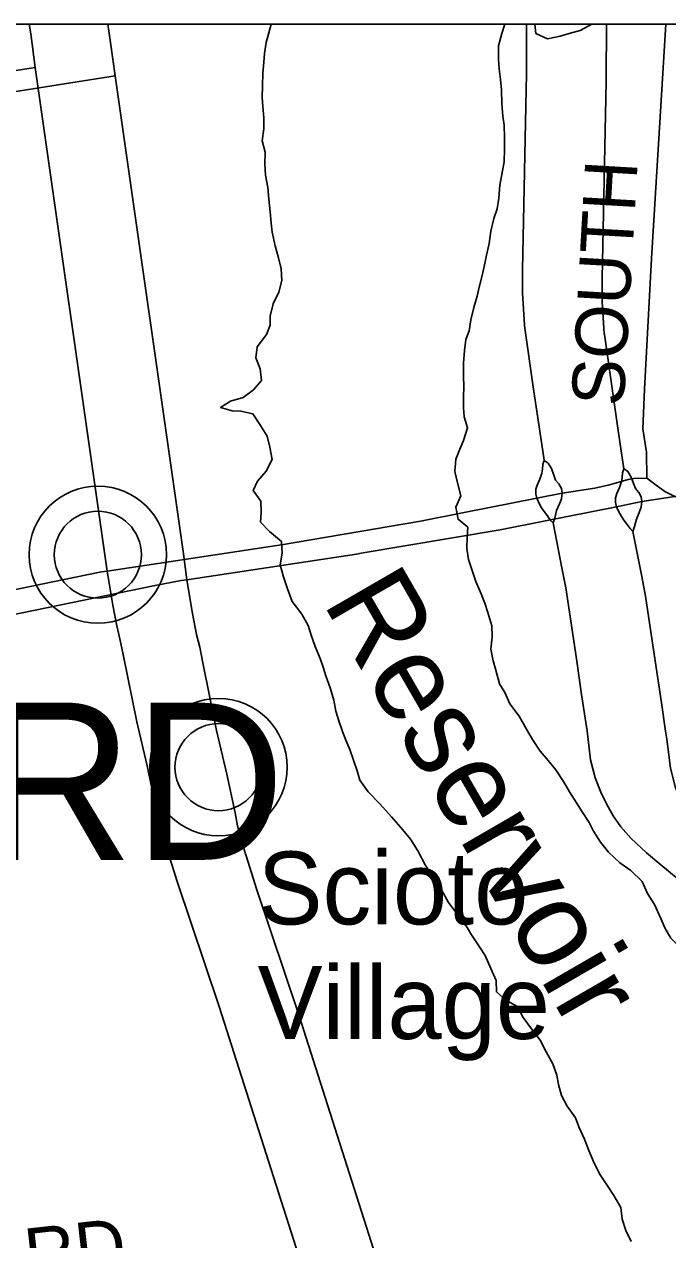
# Model space of a CAD drawing. Extents: x -38.2 to 41.9, y -4 to 24.9.
# Drawn here: x 3.416 to 4.114, y 19.582 to 20.9 of the extents above; entities that cross this region are included whole.
import ezdxf

# ---------------------------------------------------------------- set-up
doc = ezdxf.new("R2010")
doc.units = 0
for name, color, linetype in [('GM_X_County_Road', 7, 'Continuous'), ('GM_X_County_Road_Text', 7, 'Continuous'), ('GM_X_Interchange_Ramps', 7, 'Continuous'), ('GM_X_Major_Lake', 7, 'Continuous'), ('GM_X_Major_Lake_Text', 7, 'Continuous'), ('GM_X_Major_River', 7, 'Continuous'), ('GM_X_Minor_Lake', 7, 'Continuous'), ('GM_X_State_Location', 7, 'Continuous'), ('GM_X_State_Route', 7, 'Continuous'), ('GM_X_Township_Road', 7, 'Continuous'), ('GM_X_Township_Road_Text', 7, 'Continuous'), ('GM_X_Township_Text', 7, 'Continuous'), ('GM_X_Unincorporated', 7, 'Continuous'), ('GM_X_Unincorporated_Location', 7, 'Continuous'), ('GM_X_Unincorporated_Text', 7, 'Continuous'), ('SH_Cut_Line', 7, 'Continuous'), ('SH_Data', 7, 'Continuous')]:
    doc.layers.add(name, color=color, linetype=linetype)

msp = doc.modelspace()

# ---------------------------------------------------------------- linework, layer by layer
at = {"layer": 'GM_X_County_Road'}
for points in [[(4.0912, 20.4078), (4.091, 20.4359), (4.0868, 20.4612), (4.0885, 20.5043), (4.0927, 20.5786), (4.0963, 20.646), (4.1118, 20.9)], [(3.9993, 20.3916), (4.0349, 20.3972), (4.0506, 20.4007), (4.0709, 20.4065), (4.0772, 20.4075), (4.0912, 20.4078), (4.1, 20.4012), (4.1107, 20.3935), (4.1215, 20.388), (4.1348, 20.3832), (4.1455, 20.3808), (4.1717, 20.3782), (4.27, 20.374), (4.6996, 20.3515), (4.8642, 20.3433), (5.066, 20.3327)], [(3.893, 20.3705), (3.9719, 20.3861), (3.9993, 20.3916)], [(3.695, 20.3356), (3.8457, 20.3611), (3.893, 20.3705)], [(3.5061, 20.3069), (3.69, 20.3348), (3.695, 20.3356)], [(2.5521, 20.2867), (2.6398, 20.2826), (2.7282, 20.2767), (2.7828, 20.2748), (2.8413, 20.2694), (3.126, 20.2377), (3.1394, 20.236), (3.1753, 20.2401), (3.3558, 20.2767), (3.47, 20.3002), (3.5, 20.3062), (3.5061, 20.3069)]]:
    msp.add_lwpolyline(points, dxfattribs=at)
at = {"layer": 'GM_X_Interchange_Ramps'}
for p, q in [((4.0471, 20.8404), (4.0475, 20.9)), ((4.0857, 20.3013), (4.076, 20.3502))]:
    msp.add_line(p, q, dxfattribs=at)
for points in [[(5.0183, 19.2401), (5.0869, 20.3321), (5.1243, 20.9), (2.1103, 20.9), (2.1124, 20.4526), (2.1223, 20.2725), (2.1339, 19.396)], [(5.1048, 19.2309), (5.1734, 20.3229), (5.2114, 20.9), (2.1968, 20.9), (2.1989, 20.4434), (2.2088, 20.2633), (2.2204, 19.3868)], [(3.5926, 20.2977), (3.5887, 20.3257), (3.5146, 20.8441), (3.5096, 20.8803), (3.5068, 20.9)], [(4.0451, 20.5648), (4.0429, 20.5991), (4.0429, 20.6247), (4.0471, 20.8375), (4.0471, 20.8404)], [(4.0605, 20.457), (4.0549, 20.495), (4.0452, 20.5638), (4.0451, 20.5648)], [(4.0665, 20.418), (4.0664, 20.4181), (4.0605, 20.457)], [(4.076, 20.3502), (4.073, 20.3532), (4.0699, 20.3577), (4.0662, 20.3624), (4.0636, 20.3664), (4.0609, 20.3712), (4.0583, 20.3769), (4.0573, 20.3814), (4.0572, 20.3867), (4.0587, 20.3911), (4.0616, 20.3976), (4.0637, 20.4041), (4.0646, 20.4084), (4.0648, 20.4137), (4.0664, 20.4181)], [(4.0858, 20.3824), (4.0852, 20.3875), (4.0824, 20.3924), (4.0788, 20.3966), (4.0767, 20.4019), (4.0742, 20.4091), (4.0707, 20.415), (4.0665, 20.418)], [(4.076, 20.3502), (4.078, 20.3554), (4.0799, 20.3635), (4.0828, 20.3708), (4.0852, 20.3764), (4.0858, 20.3824)], [(3.9757, 18.9381), (3.9569, 19.007), (3.9527, 19.026), (3.8955, 19.2331), (3.8592, 19.3597), (3.8326, 19.4508), (3.8055, 19.539), (3.714, 19.8259), (3.6685, 19.9614), (3.651, 20.0166), (3.6474, 20.0308), (3.6447, 20.045), (3.636, 20.0869), (3.6248, 20.1343), (3.61, 20.2076), (3.6064, 20.2246), (3.6031, 20.2385), (3.5987, 20.261), (3.5926, 20.2977)], [(4.1013, 20.2027), (4.0899, 20.2798), (4.0857, 20.3013)], [(4.1116, 20.1336), (4.107, 20.1641), (4.1013, 20.2027)], [(4.3154, 19.8785), (4.3094, 19.8837), (4.247, 19.9344), (4.1928, 19.9793), (4.1772, 19.9923), (4.1603, 20.0082), (4.1494, 20.0207), (4.1411, 20.0325), (4.1341, 20.0455), (4.1278, 20.0582), (4.1218, 20.0737), (4.1167, 20.0933), (4.113, 20.1247), (4.1116, 20.1336)]]:
    msp.add_lwpolyline(points, dxfattribs=at)
at = {"layer": 'GM_X_Major_Lake'}
for points in [[(3.9573, 19.823), (3.9509, 19.8351), (3.9384, 19.842), (3.9282, 19.8508), (3.9279, 19.8633), (3.9219, 19.8762), (3.9159, 19.8902), (3.9098, 19.8997), (3.9012, 19.9127), (3.8955, 19.9225), (3.8861, 19.9347), (3.8763, 19.9476), (3.8687, 19.9613), (3.86, 19.9742), (3.851, 19.9887), (3.8431, 20.0039), (3.8348, 20.0164), (3.8246, 20.029), (3.8144, 20.0408), (3.8019, 20.0549), (3.7891, 20.0678), (3.78, 20.0804), (3.777, 20.0906), (3.7733, 20.102), (3.7691, 20.1138), (3.765, 20.1236), (3.7613, 20.1331), (3.7568, 20.1457), (3.7541, 20.1552), (3.7519, 20.1673), (3.7478, 20.1806), (3.7433, 20.1935), (3.7403, 20.203), (3.7369, 20.2125), (3.7317, 20.2254), (3.7272, 20.2376), (3.7242, 20.2482), (3.717, 20.2604), (3.7068, 20.274), (3.7016, 20.2877), (3.6974, 20.301), (3.6937, 20.3139), (3.696, 20.3264), (3.695, 20.3393), (3.6821, 20.35), (3.6723, 20.3603), (3.6731, 20.3709), (3.6727, 20.383), (3.6644, 20.3944), (3.669, 20.4047), (3.6786, 20.4156), (3.6851, 20.4281), (3.6825, 20.4414), (3.6795, 20.4535), (3.6723, 20.4649), (3.6641, 20.4775), (3.6512, 20.4806), (3.6417, 20.481), (3.6291, 20.4845), (3.6398, 20.4913), (3.6535, 20.4954), (3.6649, 20.5037), (3.6733, 20.5139), (3.6719, 20.5264), (3.6674, 20.5382), (3.6689, 20.5503), (3.6789, 20.5635), (3.6827, 20.5737), (3.6828, 20.5836), (3.6862, 20.5969), (3.6924, 20.6094), (3.6955, 20.6222), (3.6948, 20.6348), (3.6918, 20.6469), (3.6884, 20.6598), (3.6851, 20.6746), (3.684, 20.6845), (3.6829, 20.6966), (3.6814, 20.7103), (3.6803, 20.7232), (3.6777, 20.7365), (3.677, 20.7483), (3.6775, 20.7612), (3.6741, 20.7737), (3.676, 20.7866), (3.6761, 20.7987), (3.675, 20.8109), (3.6743, 20.8207), (3.6744, 20.8333), (3.6748, 20.8469), (3.676, 20.8591), (3.6768, 20.8685), (3.6784, 20.8803), (3.6814, 20.8909), (3.684, 20.9)], [(3.9373, 20.9), (3.934, 20.8901), (3.9305, 20.8765), (3.9305, 20.8617), (3.9312, 20.8518), (3.9326, 20.84), (3.9337, 20.829), (3.9341, 20.8142), (3.9351, 20.8005), (3.9366, 20.7907), (3.9369, 20.777), (3.9369, 20.7645), (3.9364, 20.7508), (3.9337, 20.7353), (3.9318, 20.7254), (3.9306, 20.7114), (3.929, 20.7), (3.9255, 20.6894), (3.9221, 20.6758), (3.9201, 20.6625), (3.9174, 20.6496), (3.915, 20.6375), (3.9127, 20.6277), (3.9096, 20.6148), (3.9073, 20.6053), (3.9038, 20.5928), (3.9004, 20.5795), (3.8984, 20.5678), (3.8949, 20.5583), (3.8934, 20.5462), (3.8926, 20.5326), (3.8925, 20.5193), (3.8928, 20.5064), (3.8924, 20.4969), (3.8923, 20.4844), (3.8931, 20.4745), (3.8968, 20.4624), (3.8926, 20.4487), (3.8883, 20.4393), (3.8841, 20.4283), (3.8829, 20.415), (3.8859, 20.4029), (3.8896, 20.3888), (3.8843, 20.3763), (3.8865, 20.3634), (3.8971, 20.3547), (3.8963, 20.3444), (3.8962, 20.3315), (3.8977, 20.3198), (3.9014, 20.3088), (3.9059, 20.2959), (3.9116, 20.2826), (3.9157, 20.2723), (3.9187, 20.2621), (3.9232, 20.2476), (3.9235, 20.2359), (3.9219, 20.2226), (3.9245, 20.2097), (3.9275, 20.1995), (3.9316, 20.185), (3.9373, 20.1755), (3.9426, 20.163), (3.9527, 20.1497), (3.9607, 20.1356), (3.9671, 20.1246), (3.9757, 20.1117), (3.9844, 20.1018), (3.9924, 20.0915), (4.001, 20.079), (4.0074, 20.0679), (4.015, 20.0558), (4.021, 20.0459), (4.0286, 20.0345), (4.0335, 20.025), (4.041, 20.0132), (4.0497, 20.0025)], [(4.0497, 20.0025), (4.0618, 19.9907), (4.0739, 19.9823), (4.086, 19.9705), (4.092, 19.9576), (4.0996, 19.9455), (4.1063, 19.9303), (4.1108, 19.9204), (4.1172, 19.909), (4.1293, 19.8972), (4.1354, 19.8839), (4.1391, 19.8718), (4.1474, 19.8584), (4.1553, 19.8455), (4.1613, 19.833), (4.1658, 19.8231), (4.1738, 19.8102), (4.1824, 19.7988), (4.1945, 19.7855), (4.2032, 19.7741), (4.2077, 19.7608), (4.2134, 19.7494)], [(4.0743, 19.5803), (4.0683, 19.592), (4.0646, 19.6042), (4.0631, 19.6171), (4.0556, 19.63), (4.0492, 19.6395), (4.0405, 19.6524), (4.0341, 19.665), (4.0285, 19.679), (4.0236, 19.6912), (4.0176, 19.7044), (4.0138, 19.7143), (4.0047, 19.7269), (3.9987, 19.7383), (3.9954, 19.7504), (3.9935, 19.7606), (3.9894, 19.7728), (3.9822, 19.7857), (3.9755, 19.7986), (3.966, 19.8108), (3.9573, 19.823)]]:
    msp.add_lwpolyline(points, dxfattribs=at)
at = {"layer": 'GM_X_Major_River'}
for points in [[(3.684, 20.9), (3.6814, 20.8909), (3.6784, 20.8803), (3.6768, 20.8685), (3.676, 20.8591), (3.6748, 20.8469), (3.6744, 20.8333), (3.6743, 20.8207), (3.675, 20.8109), (3.6761, 20.7987), (3.676, 20.7866), (3.6741, 20.7737), (3.6775, 20.7612), (3.677, 20.7483), (3.6777, 20.7365), (3.6803, 20.7232), (3.6814, 20.7103), (3.6829, 20.6966), (3.684, 20.6845), (3.6851, 20.6746), (3.6884, 20.6598), (3.6918, 20.6469), (3.6948, 20.6348), (3.6955, 20.6222), (3.6924, 20.6094), (3.6862, 20.5969), (3.6828, 20.5836), (3.6827, 20.5737), (3.6789, 20.5635), (3.6689, 20.5503), (3.6674, 20.5382), (3.6719, 20.5264), (3.6733, 20.5139), (3.6649, 20.5037), (3.6535, 20.4954), (3.6398, 20.4913), (3.6291, 20.4845), (3.6417, 20.481), (3.6512, 20.4806), (3.6641, 20.4775), (3.6723, 20.4649), (3.6795, 20.4535), (3.6825, 20.4414), (3.6851, 20.4281), (3.6786, 20.4156), (3.669, 20.4047), (3.6644, 20.3944), (3.6727, 20.383), (3.6731, 20.3709), (3.6723, 20.3603), (3.6821, 20.35), (3.695, 20.3393), (3.696, 20.3264), (3.6937, 20.3139), (3.6974, 20.301), (3.7016, 20.2877), (3.7068, 20.274), (3.717, 20.2604), (3.7242, 20.2482), (3.7272, 20.2376), (3.7317, 20.2254), (3.7369, 20.2125), (3.7403, 20.203), (3.7433, 20.1935), (3.7478, 20.1806), (3.7519, 20.1673), (3.7541, 20.1552), (3.7568, 20.1457), (3.7613, 20.1331), (3.765, 20.1236), (3.7691, 20.1138), (3.7733, 20.102), (3.777, 20.0906), (3.78, 20.0804), (3.7891, 20.0678), (3.8019, 20.0549), (3.8144, 20.0408), (3.8246, 20.029), (3.8348, 20.0164), (3.8431, 20.0039), (3.851, 19.9887), (3.86, 19.9742), (3.8687, 19.9613), (3.8763, 19.9476), (3.8861, 19.9347), (3.8955, 19.9225), (3.9012, 19.9127), (3.9098, 19.8997), (3.9159, 19.8902), (3.9219, 19.8762), (3.9279, 19.8633), (3.9282, 19.8508), (3.9384, 19.842), (3.9509, 19.8351), (3.9573, 19.823)], [(3.9373, 20.9), (3.934, 20.8901), (3.9305, 20.8765), (3.9305, 20.8617), (3.9312, 20.8518), (3.9326, 20.84), (3.9337, 20.829), (3.9341, 20.8142), (3.9351, 20.8005), (3.9366, 20.7907), (3.9369, 20.777), (3.9369, 20.7645), (3.9364, 20.7508), (3.9337, 20.7353), (3.9318, 20.7254), (3.9306, 20.7114), (3.929, 20.7), (3.9255, 20.6894), (3.9221, 20.6758), (3.9201, 20.6625), (3.9174, 20.6496), (3.915, 20.6375), (3.9127, 20.6277), (3.9096, 20.6148), (3.9073, 20.6053), (3.9038, 20.5928), (3.9004, 20.5795), (3.8984, 20.5678), (3.8949, 20.5583), (3.8934, 20.5462), (3.8926, 20.5326), (3.8925, 20.5193), (3.8928, 20.5064), (3.8924, 20.4969), (3.8923, 20.4844), (3.8931, 20.4745), (3.8968, 20.4624), (3.8926, 20.4487), (3.8883, 20.4393), (3.8841, 20.4283), (3.8829, 20.415), (3.8859, 20.4029), (3.8896, 20.3888), (3.8843, 20.3763), (3.8865, 20.3634), (3.8971, 20.3547), (3.8963, 20.3444), (3.8962, 20.3315), (3.8977, 20.3198), (3.9014, 20.3088), (3.9059, 20.2959), (3.9116, 20.2826), (3.9157, 20.2723), (3.9187, 20.2621), (3.9232, 20.2476), (3.9235, 20.2359), (3.9219, 20.2226), (3.9245, 20.2097), (3.9275, 20.1995), (3.9316, 20.185), (3.9373, 20.1755), (3.9426, 20.163), (3.9527, 20.1497), (3.9607, 20.1356), (3.9671, 20.1246), (3.9757, 20.1117), (3.9844, 20.1018), (3.9924, 20.0915), (4.001, 20.079), (4.0074, 20.0679), (4.015, 20.0558), (4.021, 20.0459), (4.0286, 20.0345), (4.0335, 20.025), (4.041, 20.0132), (4.0497, 20.0025)], [(4.0497, 20.0025), (4.0618, 19.9907), (4.0739, 19.9823), (4.086, 19.9705), (4.092, 19.9576), (4.0996, 19.9455), (4.1063, 19.9303), (4.1108, 19.9204), (4.1172, 19.909), (4.1293, 19.8972), (4.1354, 19.8839), (4.1391, 19.8718), (4.1474, 19.8584), (4.1553, 19.8455), (4.1613, 19.833), (4.1658, 19.8231), (4.1738, 19.8102), (4.1824, 19.7988), (4.1945, 19.7855), (4.2032, 19.7741), (4.2077, 19.7608), (4.2134, 19.7494)], [(3.9573, 19.823), (3.966, 19.8108), (3.9755, 19.7986), (3.9822, 19.7857), (3.9894, 19.7728), (3.9935, 19.7606), (3.9954, 19.7504), (3.9987, 19.7383), (4.0047, 19.7269), (4.0138, 19.7143), (4.0176, 19.7044), (4.0236, 19.6912), (4.0285, 19.679), (4.0341, 19.665), (4.0405, 19.6524), (4.0492, 19.6395), (4.0556, 19.63), (4.0631, 19.6171), (4.0646, 19.6042), (4.0683, 19.592), (4.0743, 19.5803)]]:
    msp.add_lwpolyline(points, dxfattribs=at)
at = {"layer": 'GM_X_Minor_Lake'}
msp.add_lwpolyline([(3.9696, 20.9), (3.971, 20.89), (3.9835, 20.8842), (3.9972, 20.8872), (4.0071, 20.8899), (4.0189, 20.8932), (4.0317, 20.9)], dxfattribs=at)
at = {"layer": 'GM_X_State_Location'}
msp.add_lwpolyline([(2.5305, 20.6559), (2.6733, 20.679), (2.8106, 20.7035), (2.9362, 20.727), (3.1099, 20.7577), (3.1121, 20.7584), (3.1169, 20.76), (3.1216, 20.7624), (3.1292, 20.7686), (3.1361, 20.7744), (3.1441, 20.7801), (3.1523, 20.7839), (3.1606, 20.7862), (3.1714, 20.7889), (3.1909, 20.7927), (3.233, 20.7996), (3.5146, 20.8441)], dxfattribs=at)
at = {"layer": 'GM_X_State_Route'}
for p, q in [((3.9606, 20.8496), (3.9609, 20.9)), ((3.9992, 20.3105), (3.9895, 20.3594))]:
    msp.add_line(p, q, dxfattribs=at)
for points in [[(3.5061, 20.3069), (3.5022, 20.3349), (3.4281, 20.8533), (3.4232, 20.8895), (3.4216, 20.9)], [(3.9586, 20.574), (3.9564, 20.6083), (3.9564, 20.6339), (3.9606, 20.8467), (3.9606, 20.8496)], [(3.9741, 20.4662), (3.9684, 20.5042), (3.9587, 20.573), (3.9586, 20.574)], [(3.98, 20.4272), (3.9799, 20.4273), (3.9741, 20.4662)], [(3.9895, 20.3594), (3.9865, 20.3623), (3.9834, 20.3669), (3.9798, 20.3716), (3.9771, 20.3756), (3.9744, 20.3804), (3.9719, 20.3861), (3.9709, 20.3906), (3.9707, 20.3959), (3.9722, 20.4003), (3.9751, 20.4068), (3.9772, 20.4133), (3.9782, 20.4176), (3.9784, 20.4228), (3.9799, 20.4273)], [(3.9993, 20.3916), (3.9987, 20.3967), (3.9959, 20.4016), (3.9923, 20.4058), (3.9903, 20.4111), (3.9878, 20.4183), (3.9842, 20.4242), (3.98, 20.4272)], [(3.9895, 20.3594), (3.9915, 20.3645), (3.9934, 20.3727), (3.9964, 20.38), (3.9987, 20.3856), (3.9993, 20.3916)], [(4.0148, 20.2119), (4.0034, 20.289), (3.9992, 20.3105)], [(3.8893, 18.9473), (3.8705, 19.0162), (3.8662, 19.0352), (3.809, 19.2422), (3.7727, 19.3689), (3.7462, 19.46), (3.7191, 19.5482), (3.6275, 19.835), (3.582, 19.9706), (3.5645, 20.0257), (3.561, 20.04), (3.5582, 20.0542), (3.5495, 20.0961), (3.5384, 20.1435), (3.5235, 20.2168), (3.5199, 20.2338), (3.5166, 20.2477), (3.5122, 20.2701), (3.5061, 20.3069)], [(4.0252, 20.1428), (4.0205, 20.1733), (4.0148, 20.2119)], [(4.2289, 19.8876), (4.2229, 19.8929), (4.1606, 19.9436), (4.1063, 19.9885), (4.0907, 20.0015), (4.0738, 20.0174), (4.0629, 20.0299), (4.0546, 20.0417), (4.0476, 20.0547), (4.0413, 20.0674), (4.0353, 20.0829), (4.0302, 20.1024), (4.0265, 20.1339), (4.0252, 20.1428)]]:
    msp.add_lwpolyline(points, dxfattribs=at)
at = {"layer": 'GM_X_Township_Road'}
msp.add_lwpolyline([(2.444, 20.6651), (2.5868, 20.6882), (2.7242, 20.7127), (2.8497, 20.7362), (3.0234, 20.7669), (3.0256, 20.7676), (3.0304, 20.7692), (3.0351, 20.7716), (3.0428, 20.7777), (3.0496, 20.7836), (3.0576, 20.7892), (3.0658, 20.7931), (3.0742, 20.7954), (3.085, 20.7981), (3.1045, 20.8019), (3.1465, 20.8088), (3.4281, 20.8533)], dxfattribs=at)
at = {"layer": 'GM_X_Township_Road_Text'}
for points in [[(4.0858, 20.3824), (4.1214, 20.388), (4.137, 20.3915), (4.1574, 20.3973), (4.1637, 20.3983), (4.1777, 20.3987), (4.1865, 20.3921), (4.1972, 20.3843), (4.208, 20.3788), (4.2213, 20.374), (4.232, 20.3716), (4.2582, 20.369), (4.3565, 20.3648), (4.7861, 20.3423), (4.9507, 20.3341), (5.1524, 20.3235)], [(3.9795, 20.3613), (4.0583, 20.3769), (4.0858, 20.3824)], [(3.7814, 20.3264), (3.9321, 20.3519), (3.9795, 20.3613)], [(3.5926, 20.2977), (3.7765, 20.3256), (3.7814, 20.3264)], [(2.6386, 20.2775), (2.7263, 20.2734), (2.8147, 20.2675), (2.8693, 20.2656), (2.9277, 20.2602), (3.2124, 20.2285), (3.2258, 20.2268), (3.2617, 20.2309), (3.4423, 20.2675), (3.5565, 20.2911), (3.5864, 20.297), (3.5926, 20.2977)]]:
    msp.add_lwpolyline(points, dxfattribs=at)
at = {"layer": 'GM_X_Unincorporated'}
for centre, radius in [((3.496, 20.3249), 0.0744), ((3.496, 20.3249), 0.0472), ((3.6268, 20.0945), 0.0744), ((3.6268, 20.0945), 0.0472)]:
    msp.add_circle(centre, radius, dxfattribs=at)
at = {"layer": 'GM_X_Unincorporated_Location'}
for p, q in [((3.496, 20.3249), (3.496, 20.3249)), ((3.6268, 20.0945), (3.6268, 20.0945))]:
    msp.add_line(p, q, dxfattribs=at)
at = {"layer": 'SH_Cut_Line'}
msp.add_lwpolyline([(8.9, 20.9), (2.1103, 20.9), (2.1124, 20.4526), (2.1223, 20.2725), (2.1339, 19.396), (2.138, 18.8976), (2.1421, 18.2952), (2.1429, 18.1709), (2.1427, 17.838), (2.1422, 17.7563), (2.1521, 17.6416), (2.1549, 17.5972), (2.1569, 17.5704), (2.1486, 17.1556)], dxfattribs=at)
at = {"layer": 'SH_Data'}
msp.add_line((2.1, 20.9), (8.9, 20.9), dxfattribs=at)

# ---------------------------------------------------------------- texts
at = {"layer": 'GM_X_County_Road_Text'}
msp.add_text('SOUTH', height=0.05682, rotation=86.6936, dxfattribs=at).set_placement((4.066, 20.4851))
at = {"layer": 'GM_X_Major_Lake_Text'}
msp.add_text('Reservoir', height=0.09457, rotation=300.0355, dxfattribs=at).set_placement((3.739, 20.2734))
at = {"layer": 'GM_X_Township_Road_Text'}
msp.add_text('RD', height=0.05682, rotation=6.4498, dxfattribs=at).set_placement((3.42, 19.5371))
at = {"layer": 'GM_X_Township_Text'}
msp.add_text('CONCORD', height=0.17045, rotation=0, dxfattribs=at).set_placement((2.5215, 19.994))
at = {"layer": 'GM_X_Unincorporated_Text'}
for s, p in [('Scioto', (3.6692, 19.924)), ('Village', (3.6692, 19.7998))]:
    msp.add_text(s, height=0.07898, rotation=0, dxfattribs=at).set_placement(p)

doc.saveas('drawing.dxf')
